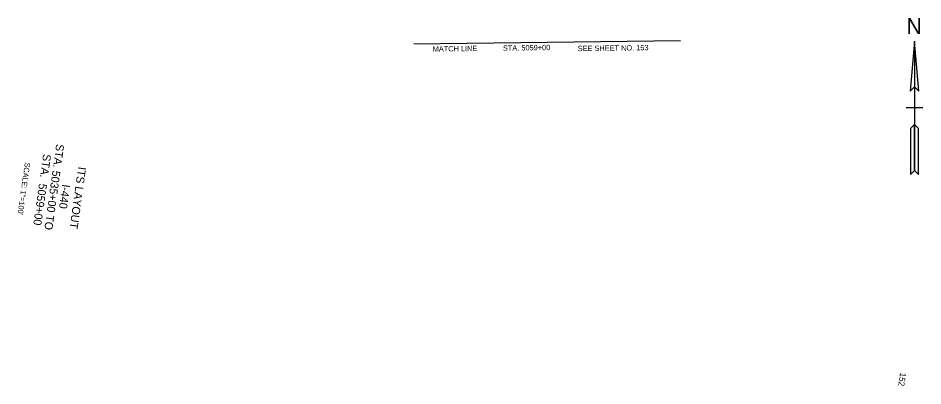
# Model space of a CAD drawing. Extents: x -200 to 1726453, y -325 to 661349.
# Drawn here: x 1724419 to 1726453, y 658155 to 658981 of the extents above; entities that cross this region are included whole.
import ezdxf

# ---------------------------------------------------------------- set-up
doc = ezdxf.new("R2010")
doc.units = 0
for name, color, linetype in [('DESIGN - CENTERLINE - Proposed Text', 7, 'Continuous'), ('DESIGN - SHEET - Corner Text', 7, 'Continuous'), ('ITS - CONST TEXT', 7, 'Continuous'), ('ITS - EXISTING COMM CABLE', 7, 'Continuous'), ('ITS - EXISTING HAR', 7, 'Continuous')]:
    doc.layers.add(name, color=color, linetype=linetype)

msp = doc.modelspace()

# ---------------------------------------------------------------- linework, layer by layer
at = {"layer": 'DESIGN - CENTERLINE - Proposed Text'}
for p, q in [((1726434.1, 658779.5), (1726415.2, 658779.5)), ((1726453, 658779.5), (1726434.1, 658779.5))]:
    msp.add_line(p, q, dxfattribs=at)
msp.add_lwpolyline([(1726434.1, 658929.5), (1726424.3, 658816.9), (1726434.1, 658826.7), (1726443.9, 658816.9), (1726434.1, 658929.5), (1726434.1, 658638.6), (1726443.2, 658629.5), (1726443.2, 658733), (1726434.1, 658742.1), (1726425, 658733), (1726425, 658629.5), (1726434.1, 658638.6)], dxfattribs=at)
for points in [[(1726434.1, 658826.7), (1726443.9, 658816.9), (1726434.1, 658929.5)], [(1726425, 658629.5), (1726434.1, 658638.6), (1726434.1, 658742.1), (1726425, 658733)]]:
    msp.add_lwpolyline(points, close=True, dxfattribs=at)
at = {"layer": 'ITS - EXISTING COMM CABLE'}
msp.add_line((1725308.1, 658923), (1725908, 658931), dxfattribs=at)

# ---------------------------------------------------------------- texts
at = {"layer": 'DESIGN - CENTERLINE - Proposed Text'}
msp.add_text('N', height=35.4, dxfattribs=at).set_placement((1726416, 658945.6))
at = {"layer": 'DESIGN - SHEET - Corner Text'}
msp.add_text('152', height=13.5, rotation=262.045, dxfattribs=at).set_placement((1726401.7, 658184.9))
at = {"layer": 'ITS - CONST TEXT'}
msp.add_text('SCALE: 1"=100\'', height=12, rotation=262.0451, dxfattribs=at).set_placement((1724434.1, 658657.3))
at = {"layer": 'ITS - EXISTING COMM CABLE'}
for s, p in [('STA. 5059+00', (1725508.9, 658907.7)), ('SEE SHEET NO. 153 ', (1725676.9, 658906.7)), ('MATCH LINE', (1725350.9, 658905.6))]:
    msp.add_text(s, height=12, rotation=0.7663, dxfattribs=at).set_placement(p)
at = {"layer": 'ITS - EXISTING HAR'}
for s, p in [('STA. 5035+00 TO', (1724504.6, 658698.9)), ('STA.  5059+00', (1724475.2, 658676.4)), ('ITS LAYOUT', (1724553.9, 658647.7)), ('I-440', (1724518.2, 658608.3))]:
    msp.add_text(s, height=18, rotation=262.0451, dxfattribs=at).set_placement(p)

doc.saveas('drawing.dxf')
